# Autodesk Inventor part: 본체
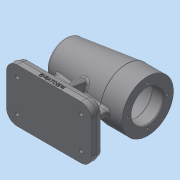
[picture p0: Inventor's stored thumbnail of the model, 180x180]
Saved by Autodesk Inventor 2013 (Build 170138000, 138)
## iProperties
Created: 2017-01
Part Number: 본체
Material: 일반
Document SubType Name: Modeling
Designer: dgall
Density: 1 g/cm^3
Author: dgall
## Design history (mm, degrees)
sketch "스케치1"
  geometry: L1 (-56, 0)-(56, 0); L2 (56, 0)-(56, 34); L3 (56, 34)-(28, 34); L4 (28, 34)-(-52.27, 24.144); L5 (56, 21)-(41, 21); L6 (41, 21)-(41, 24); L7 (41, 24)-(-13, 24); L8 (-13, 24)-(-13, 21); L9 (-13, 21)-(-25, 21); L10 (-25, 21)-(-25, 17.5); L11 (-25, 17.5)-(-43, 17.5); L12 (-43, 17.5)-(-43, 16); L13 (-43, 16)-(-47, 16); L14 (-47, 16)-(-47, 10.5); L15 (-47, 10.5)-(-50, 10.5); L16 (-50, 10.5)-(-50, 0); A1 r 80 centre (24, 0) between (-52.27, 24.144) and (-56, 0); 2 further points
  constraints: 32 end point, 10 parallel, 3 perpendicular, 2 collinear, 2 point on circle, 2 point on line, 1 centre point, 1 coincident, 1 horizontal, 1 horizontal alignment, 1 midpoint
  dimensions: "d0" = 112 distance of L1.start L1.end; "d2" = 68 diameter of L3 L1; "d3" = 80 radius of A1; "d4" = 7 deg angle of L4 L3; "d5" = 28 distance of L2.end L3.end; "d6" = 48 diameter of L7 L1; "d7" = 42 diameter of L5 L1; "d9" = 35 diameter of L11 L1; "d10" = 32 diameter of L13 L1; "d11" = 21 diameter of L15 L1; "d12" = 15 distance of L5.start L5.end; "d13" = 54 distance of L6.end L7.end; "d14" = 3 distance of L14.end L15.end; "d15" = 4 distance of L12.end L13.end; "d16" = 18 distance of L10.end L11.end; "d17" = 12 distance of L8.end L9.end
revolve "회전1" sketch "스케치1" stored, may be unused: angle "d18" = 90 deg
node "작업 평면1"
sketch "스케치2"
  geometry: L1 (-56, 34)-(-56, -34) reference; L2 (-56, -35)-(56, -35); L3 (56, -35)-(56, 35); L4 (56, 35)-(-56, 35); L5 (-56, 35)-(-56, -35); 2 further points
  constraints: 8 end point, 2 parallel, 1 collinear, 1 horizontal, 1 horizontal alignment, 1 midpoint, 1 perpendicular
  dimensions: "d20" = 112 distance of L2.start L2.end; "d22" = 70 distance of L4.end L2.start
extrude "돌출1" join sketch "스케치2" distance "d23" = 7; taper "d24" = 0 deg
fillet "모깎기1" dims "d25" = 14
sketch "스케치3"
  geometry: L1 (42, 35)-(-42, 35) reference; L2 (-56, 21)-(-56, -21) reference; L3 (-42, -35)-(42, -35) reference; L4 (56, -21)-(56, 21) reference; A1 r 14 centre (42, 21) between (56, 21) and (42, 35) reference; A2 r 14 centre (-42, 21) between (-42, 35) and (-56, 21) reference; A3 r 14 centre (-42, -21) between (-56, -21) and (-42, -35) reference; A4 r 14 centre (42, -21) between (42, -35) and (56, -21) reference; 1 further point
extrude "돌출2" join sketch "스케치3" distance "d26" = 7; taper "d27" = -15 deg
sketch "스케치4"
  geometry: L1 (-74, -35)-(-74, 35) reference; L2 (-74, 35)-(-67, 35) reference; L3 (-67, 35)-(-60, 33.124) reference; L4 (-60, 33.124)-(-60, -33.124) reference; L5 (-60, -33.124)-(-67, -35) reference; L6 (-67, -35)-(-74, -35) reference; L7 (-18.211, 15.632)-(-60, 23); L8 (-18.211, -15.632)-(-60, -23); C1 r 30.562 at (0, 0) reference; A1 r 24 centre (0, 0) between (-18.211, 15.632) and (-18.211, -15.632) reference; 1 further point
  constraints: 4 end point, 2 point on circle, 2 point on line, 1 equal length
  dimensions: "d30" = 100 deg angle of L4 L7; "d31" = 100 deg angle of L4 L8; "d32" = 12 distance from line of L2 L7.end
extrude "돌출3" join sketch "스케치4" stored distance "d33" = 8; taper "d34" = 0 deg
sketch "스케치5"
  geometry: L1 (56, -74)-(-56, -74) reference; L2 (-56, -74)-(-56, -67) reference; L3 (-56, -67)-(-54.124, -60) reference; L4 (-54.124, -60)-(-4, -60) reference; L5 (-4, -60)-(-4, -30.071) reference; L6 (-4, -30.071)-(-52.27, -24.144) reference; L7 (-52.27, 24.144)-(28, 34) reference; L8 (28, 34)-(56, 34) reference; L9 (56, 34)-(56, 21) reference; L10 (56, 21)-(41, 21) reference; L11 (41, 21)-(41, 24) reference; L12 (41, 24)-(-13, 24) reference; L13 (-13, 24)-(-13, 21) reference; L14 (-13, 21)-(-25, 21) reference; L15 (-25, 21)-(-25, 17.5) reference; L16 (-25, 17.5)-(-43, 17.5) reference; L17 (-43, 17.5)-(-43, 16) reference; L18 (-43, 16)-(-47, 16) reference; L19 (-47, 16)-(-47, 10.5) reference; L20 (-47, 10.5)-(-50, 10.5) reference; L21 (-50, 10.5)-(-50, -10.5) reference; L22 (-50, -10.5)-(-47, -10.5) reference; L23 (-47, -10.5)-(-47, -16) reference; L24 (-47, -16)-(-43, -16) reference; L25 (-43, -16)-(-43, -17.5) reference; L26 (-43, -17.5)-(-25, -17.5) reference; L27 (-25, -17.5)-(-25, -21) reference; L28 (-25, -21)-(-13, -21) reference; L29 (-13, -21)-(-13, -24) reference; L30 (-13, -24)-(41, -24) reference; L31 (41, -24)-(41, -21) reference; L32 (41, -21)-(56, -21) reference; L33 (56, -21)-(56, -34) reference; L34 (56, -34)-(28, -34) reference; L35 (28, -34)-(4, -31.053) reference; L36 (4, -31.053)-(4, -60) reference; L37 (4, -60)-(54.124, -60) reference; L38 (54.124, -60)-(56, -67) reference; L39 (56, -67)-(56, -74) reference; L40 (-38, -25.896)-(-38, -60); L41 (38, -34)-(38, -60); A1 r 80 centre (24, 0) between (-52.27, 24.144) and (-52.27, -24.144) reference; 1 further point
  constraints: 4 end point, 4 point on line, 2 perpendicular
  dimensions: "d35" = 18 distance between parallel lines of L2 L40; "d36" = 18 distance between parallel lines of L39 L41
  node "절단 모서리 투영2"
feature "리브1" dims "d37" = 1, "d38" = 8, "d39" = 0, "d40" = 0, "d41" = 1, "d42" = 1
feature "리브2" dims "d43" = 1, "d44" = 8, "d45" = 0, "d46" = 0, "d47" = 1, "d48" = 1
sketch "스케치6" dims "d49" = 5
  geometry: L1 (-39.113, 26)-(-36.226, 21); L2 (-36.226, 21)-(-39.113, 16); L3 (-39.113, 16)-(-44.887, 16); L4 (-44.887, 16)-(-47.774, 21); L5 (-47.774, 21)-(-44.887, 26); L6 (-44.887, 26)-(-39.113, 26); L7 (-39.113, -16)-(-36.226, -21); L8 (-36.226, -21)-(-39.113, -26); L9 (-39.113, -26)-(-44.887, -26); L10 (-44.887, -26)-(-47.774, -21); L11 (-47.774, -21)-(-44.887, -16); L12 (-44.887, -16)-(-39.113, -16); L13 (44.887, -16)-(47.774, -21); L14 (47.774, -21)-(44.887, -26); L15 (44.887, -26)-(39.113, -26); L16 (39.113, -26)-(36.226, -21); L17 (36.226, -21)-(39.113, -16); L18 (39.113, -16)-(44.887, -16); L19 (44.887, 26)-(47.774, 21); L20 (47.774, 21)-(44.887, 16); L21 (44.887, 16)-(39.113, 16); L22 (39.113, 16)-(36.226, 21); L23 (36.226, 21)-(39.113, 26); L24 (39.113, 26)-(44.887, 26); A1 r 12.124 centre (-42, -21) between (-54.124, -21) and (-42, -33.124) reference; A2 r 12.124 centre (42, -21) between (42, -33.124) and (54.124, -21) reference; A3 r 12.124 centre (42, 21) between (54.124, 21) and (42, 33.124) reference; A4 r 12.124 centre (-42, 21) between (-42, 33.124) and (-54.124, 21) reference; 13 further points
  constraints: 48 end point, 8 coincident, 8 vertical alignment, 4 midpoint, 60 other
extrude "돌출4" cut sketch "스케치6" distance "d51" = 4; taper "d52" = 0 deg
sketch "스케치7"
  geometry: A1 r 14 centre (-42, -21) between (-56, -21) and (-42, -35) reference; A2 r 14 centre (42, -21) between (42, -35) and (56, -21) reference; A3 r 14 centre (42, 21) between (56, 21) and (42, 35) reference; A4 r 14 centre (-42, 21) between (-42, 35) and (-56, 21) reference; 1 further point
hole "구멍1" sketch "스케치7" at (-42, 21), (-42, -21), (42, 21), (42, -21) diameter "d53" = 5; stored, may be unused: countersink angle "d57" = 90 deg, drill point angle "d59" = 118 deg; dims "d54" = 6, "d55" = 4, "d56" = 2, "d58" = 14
fillet "모깎기2" dims "d60" = 1
fillet "모깎기3" dims "d61" = 3
fillet "모깎기4" dims "d62" = 3
fillet "모깎기5" dims "d63" = 0.3
sketch "스케치8"
  geometry: L1 (98, 0)-(98, 7) reference; L2 (98, 0)-(84, 0) reference; 2 further points
  constraints: 1 other
  dimensions: "d64" = 56 distance from line of L1 point (42, 4); "d65" = 4 distance from line of L2 point (42, 4)
extrude "돌출5" join sketch "스케치8" distance "d66" = 0.5; taper "d67" = 0 deg
sketch "스케치9"
  geometry: C1 r 34 at (0, 0) reference; 1 further point
  constraints: 1 vertical alignment
  dimensions: "d68" = 26 distance of C1.centre point (0, 26)
hole "구멍2" sketch "스케치9" at (0, 26) diameter "d69" = 3.242; stored, may be unused: countersink angle "d73" = 90 deg, drill point angle "d75" = 118 deg; dims "d70" = 8, "d71" = 4, "d72" = 2, "d74" = 11
chamfer "모따기1" distance "d79" = 1; stored, may be unused: second distance "d80" = 2, angle "d81" = 45 deg
node "솔리드1"
pattern_circular "원형 패턴1" dims angle "d77" = 360 deg
node "절단 모서리 투영1"
other parameters: "d19" = -74
